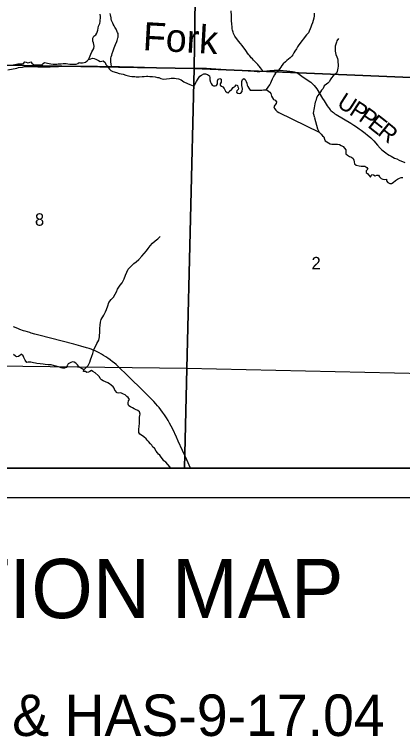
# Model space of a CAD drawing. Extents: x 0 to 34, y 0 to 22.
# Drawn here: x 13.836 to 15.148, y 12.694 to 15.132 of the extents above; entities that cross this region are included whole.
import ezdxf

# ---------------------------------------------------------------- set-up
doc = ezdxf.new("R2010")
doc.units = 0
for name, color, linetype in [('GM_X_Corporation', 7, 'Continuous'), ('GM_X_County_Road', 7, 'Continuous'), ('GM_X_County_Road_Text', 7, 'Continuous'), ('GM_X_Minor_River', 7, 'Continuous'), ('GM_X_Minor_River_Text', 7, 'Continuous'), ('GM_X_Section_Text', 7, 'Continuous'), ('GM_X_State_Route', 7, 'Continuous'), ('GM_X_Township_Road', 7, 'Continuous'), ('SH_Data', 7, 'Continuous'), ('SH_Text', 7, 'Continuous')]:
    doc.layers.add(name, color=color, linetype=linetype)

msp = doc.modelspace()

# ---------------------------------------------------------------- linework, layer by layer
at = {"layer": 'GM_X_Corporation'}
for points in [[(13.4336, 15.974), (14.4583, 15.9623), (14.443, 14.9501), (13.4208, 14.9679)], [(14.4583, 15.9623), (15.4691, 15.9163), (15.4475, 14.9085), (14.443, 14.9501)], [(13.4208, 14.9679), (14.443, 14.9501), (14.4181, 13.9369), (13.4018, 13.9496)], [(14.443, 14.9501), (15.4475, 14.9085), (15.4212, 13.9143), (14.4181, 13.9369)], [(13.3964, 13.6), (14.411, 13.6), (14.4181, 13.9369), (13.4018, 13.9496)], [(14.411, 13.6), (15.4145, 13.6), (15.4212, 13.9143), (14.4181, 13.9369)]]:
    msp.add_lwpolyline(points, close=True, dxfattribs=at)
msp.add_lwpolyline([(10.9052, 15.3502), (10.897, 14.5214), (10.8818, 13.7678), (10.8788, 13.6), (16.4214, 13.6), (16.4212, 13.6609), (16.4339, 14.3806), (16.438, 14.5908), (16.4419, 14.8642), (16.4498, 15.4626)], dxfattribs=at)
at = {"layer": 'GM_X_County_Road'}
msp.add_lwpolyline([(13.8138, 14.9451), (13.8435, 14.9513), (13.8499, 14.9526), (13.8627, 14.9546), (13.867, 14.9552), (13.8765, 14.956), (13.8824, 14.9562), (13.8912, 14.9564), (13.9031, 14.9563), (13.9149, 14.9558), (13.9236, 14.9554), (13.9506, 14.9549), (13.957, 14.9549), (14.0131, 14.9573), (14.0251, 14.9575), (14.0534, 14.9577), (14.117, 14.957), (14.1283, 14.9569), (14.1636, 14.9571), (14.2187, 14.9553), (14.238, 14.9549), (14.3484, 14.9524), (14.3663, 14.952), (14.4643, 14.9512), (14.474, 14.951), (14.4849, 14.9503), (14.5494, 14.9465), (14.5665, 14.9455), (14.6262, 14.9414), (14.6455, 14.9403), (14.6557, 14.9399), (14.6648, 14.9399), (14.6725, 14.9401), (14.6751, 14.9402), (14.6792, 14.9405), (14.6988, 14.9425), (14.7062, 14.9432), (14.7135, 14.9438), (14.7207, 14.9442), (14.7278, 14.944), (14.735, 14.9436), (14.7441, 14.9429), (14.7564, 14.9415), (14.7669, 14.9403), (14.7743, 14.9394), (14.7772, 14.9388), (14.7809, 14.938), (14.785, 14.9368), (14.7881, 14.9357), (14.7977, 14.9306), (14.8121, 14.9207), (14.824, 14.9125), (14.8321, 14.9067), (14.837, 14.9031), (14.8423, 14.8989), (14.8489, 14.892), (14.8532, 14.8868), (14.8573, 14.8813), (14.8768, 14.8488), (14.8822, 14.8401), (14.8926, 14.8241), (14.8958, 14.8195), (14.8981, 14.8164), (14.9033, 14.8105), (14.9056, 14.8082), (14.9108, 14.8034), (14.9136, 14.801), (14.919, 14.797), (14.9228, 14.7945), (14.9724, 14.7651), (14.9827, 14.7588), (14.992, 14.7526), (15.001, 14.7462), (15.008, 14.7411), (15.0214, 14.731), (15.0288, 14.7251), (15.0339, 14.7211), (15.0403, 14.7154), (15.045, 14.7109), (15.0506, 14.7049), (15.0633, 14.6905), (15.0723, 14.6811), (15.0777, 14.6755), (15.0816, 14.672), (15.0861, 14.6683), (15.0906, 14.6648), (15.097, 14.6601), (15.1026, 14.6568), (15.1093, 14.6531), (15.1149, 14.6502), (15.1208, 14.6472), (15.1277, 14.6441), (15.1366, 14.6403), (15.1556, 14.6327)], dxfattribs=at)
at = {"layer": 'GM_X_Minor_River'}
for points in [[(13.8616, 14.9658), (13.8666, 14.967), (13.8711, 14.9723), (13.876, 14.9708), (13.8806, 14.9689), (13.8859, 14.9704), (13.8912, 14.9727), (13.8947, 14.9674), (13.9007, 14.9629), (13.9057, 14.9617), (13.9232, 14.9618), (13.9285, 14.9622), (13.933, 14.9671), (13.9376, 14.9694), (13.9433, 14.969), (13.9478, 14.9679), (13.9531, 14.9668), (13.9588, 14.9656), (13.9668, 14.9645), (13.9786, 14.9645), (13.9839, 14.9653), (13.9884, 14.9657), (13.9938, 14.9657), (14.0002, 14.9665), (14.0067, 14.9661), (14.0112, 14.9661), (14.0158, 14.9654), (14.023, 14.9642), (14.0279, 14.9642), (14.0332, 14.9642), (14.0401, 14.9639), (14.045, 14.9643), (14.0496, 14.9666), (14.0541, 14.9696), (14.0587, 14.9692), (14.0659, 14.9685), (14.0716, 14.9696), (14.0765, 14.9712), (14.0818, 14.9754), (14.0864, 14.9799), (14.0894, 14.9864), (14.0916, 14.9929), (14.0935, 14.9982), (14.0973, 15.0058), (14.1007, 15.0119), (14.1041, 15.0172), (14.1052, 15.0252), (14.1044, 15.0309), (14.1025, 15.0358), (14.101, 15.0423), (14.1006, 15.0476), (14.1009, 15.0521), (14.1043, 15.0586), (14.1104, 15.0628), (14.1146, 15.0689), (14.1172, 15.0788), (14.1187, 15.086), (14.1202, 15.0921), (14.1239, 15.1012), (14.1254, 15.108), (14.1258, 15.1134), (14.1269, 15.1194), (14.1269, 15.1248), (14.1261, 15.1335)], [(14.8488, 15.1361), (14.849, 15.1278), (14.8473, 15.1201), (14.8453, 15.1113), (14.8428, 15.1044), (14.8403, 15.0956), (14.8378, 15.0891), (14.8353, 15.0833), (14.8317, 15.0757), (14.83, 15.0703), (14.8233, 15.0629)], [(14.8233, 15.0629), (14.7973, 15.0299), (14.7924, 15.0227), (14.789, 15.0166), (14.7837, 15.0086), (14.7803, 15.0025), (14.7765, 14.996), (14.7728, 14.9911), (14.7675, 14.9861), (14.7561, 14.977), (14.7515, 14.9724), (14.7436, 14.9656), (14.7394, 14.9595), (14.736, 14.9545), (14.7326, 14.9496), (14.7273, 14.9431), (14.7236, 14.9386), (14.7186, 14.934), (14.7149, 14.9287), (14.7103, 14.9203), (14.7069, 14.9131), (14.7039, 14.9058), (14.7013, 14.9001), (14.6986, 14.8956), (14.6941, 14.8895), (14.6899, 14.883), (14.685, 14.8781)], [(14.9314, 15.0504), (14.9259, 15.0434), (14.9245, 15.0381), (14.922, 15.0319), (14.9199, 15.025), (14.9203, 15.0087), (14.9208, 15.003), (14.9225, 14.997), (14.9257, 14.9891), (14.9278, 14.9834), (14.9287, 14.9777), (14.9292, 14.9709), (14.9294, 14.9637), (14.9299, 14.9576), (14.9293, 14.9511), (14.9262, 14.9393), (14.9241, 14.9339), (14.9181, 14.9296), (14.9125, 14.9249), (14.907, 14.9179), (14.9034, 14.9117), (14.9009, 14.9056), (14.8953, 14.9005), (14.8901, 14.8962), (14.8831, 14.8907), (14.8795, 14.8826), (14.8739, 14.8764), (14.8699, 14.8706), (14.8655, 14.864), (14.8611, 14.8586), (14.8571, 14.8501), (14.8543, 14.8409), (14.8526, 14.8355), (14.8516, 14.8298), (14.8498, 14.8233), (14.8485, 14.8168), (14.8475, 14.8111), (14.8465, 14.8046), (14.8459, 14.7985), (14.8497, 14.7838)], [(14.0866, 14.9804), (14.0943, 14.9822), (14.1, 14.9849), (14.1049, 14.9838), (14.1106, 14.9815), (14.1152, 14.9792), (14.1198, 14.9762), (14.1259, 14.9732), (14.1316, 14.9739), (14.1361, 14.9755), (14.143, 14.9698), (14.1453, 14.9633), (14.1502, 14.9572), (14.154, 14.9523), (14.1567, 14.9478), (14.1616, 14.9428), (14.1681, 14.939), (14.181, 14.9356), (14.1901, 14.933), (14.2038, 14.9304), (14.2126, 14.9273), (14.2209, 14.9251), (14.2259, 14.924), (14.2323, 14.9228), (14.2376, 14.9228), (14.2429, 14.9221), (14.2475, 14.9213), (14.2521, 14.921), (14.257, 14.9214), (14.2672, 14.9225), (14.2741, 14.9229), (14.2821, 14.9233), (14.2866, 14.9237), (14.2934, 14.9229), (14.3026, 14.9222), (14.3113, 14.9211), (14.3193, 14.9196), (14.3238, 14.9188), (14.3303, 14.9158), (14.3356, 14.9143), (14.3409, 14.9139), (14.3497, 14.9143), (14.3603, 14.9158), (14.366, 14.9166), (14.3721, 14.917), (14.3766, 14.917), (14.3827, 14.9155), (14.3907, 14.9148), (14.3998, 14.9114), (14.4085, 14.9042), (14.4203, 14.8992), (14.4283, 14.8958), (14.4401, 14.8909), (14.4458, 14.8955), (14.4511, 14.9054), (14.4545, 14.9118), (14.4575, 14.9168), (14.4624, 14.924), (14.4685, 14.9271), (14.476, 14.9313), (14.4817, 14.9313), (14.4878, 14.9298), (14.4947, 14.9245), (14.4966, 14.9184), (14.4962, 14.9112), (14.4985, 14.9032), (14.5004, 14.8986), (14.5039, 14.8937), (14.5088, 14.8914), (14.5137, 14.891), (14.5183, 14.8926), (14.5217, 14.8975), (14.5221, 14.9032), (14.522, 14.9082), (14.5243, 14.9131), (14.53, 14.9154), (14.5346, 14.9135), (14.535, 14.9089), (14.5342, 14.9032), (14.5316, 14.8983), (14.5308, 14.893), (14.5358, 14.8899), (14.5407, 14.8873), (14.5441, 14.8824), (14.5491, 14.8736), (14.5544, 14.8691), (14.5594, 14.8672), (14.562, 14.8718), (14.5703, 14.8801), (14.5753, 14.8858), (14.5817, 14.89), (14.5855, 14.8946), (14.5901, 14.8923), (14.5908, 14.8874), (14.5927, 14.8828), (14.592, 14.8783), (14.5871, 14.8745), (14.5863, 14.8695), (14.5913, 14.8661), (14.5962, 14.8654), (14.6008, 14.8661)], [(13.832, 14.9616), (13.8377, 14.9631), (13.8423, 14.9643), (13.8468, 14.965), (13.8525, 14.9651), (13.8616, 14.9658)], [(14.6008, 14.8661), (14.6053, 14.8715), (14.6064, 14.8817), (14.6045, 14.8924), (14.6041, 14.9003), (14.6048, 14.906), (14.6063, 14.9121), (14.6109, 14.9159), (14.6154, 14.9125), (14.6185, 14.9061), (14.6212, 14.9), (14.6223, 14.8935), (14.6246, 14.8886), (14.6277, 14.8829), (14.633, 14.8764), (14.6376, 14.8761), (14.6436, 14.8765), (14.6508, 14.8765), (14.6581, 14.8761), (14.6672, 14.8761), (14.6721, 14.8765), (14.6774, 14.8773), (14.685, 14.8781), (14.6896, 14.8766), (14.6945, 14.8735), (14.6995, 14.8701), (14.7029, 14.8652), (14.7037, 14.8606), (14.7048, 14.8557), (14.7079, 14.8511), (14.7117, 14.8451), (14.7166, 14.8428), (14.7212, 14.8371), (14.7205, 14.8318), (14.7159, 14.8253), (14.7121, 14.8207), (14.7148, 14.8147), (14.7198, 14.8093), (14.7243, 14.8044), (14.7293, 14.8014), (14.8657, 14.7347)], [(14.8499, 14.7835), (14.8601, 14.7464), (14.8618, 14.7411), (14.8657, 14.7347), (14.8723, 14.728), (14.8766, 14.7225), (14.882, 14.7192), (14.8834, 14.7112), (14.8862, 14.7052), (14.892, 14.7019), (14.8973, 14.6986), (14.9031, 14.6957), (14.9088, 14.6944), (14.9157, 14.6942), (14.9225, 14.6943), (14.9278, 14.6941), (14.9339, 14.6927), (14.9405, 14.6891), (14.9473, 14.6866), (14.9517, 14.6806), (14.9556, 14.6746), (14.9554, 14.667), (14.9556, 14.6617), (14.9614, 14.6565), (14.9683, 14.6525), (14.9748, 14.65), (14.981, 14.6463), (14.9834, 14.6399), (14.9839, 14.6343), (14.9849, 14.6274), (14.9903, 14.6238), (15.0013, 14.6214), (15.0074, 14.62), (15.0143, 14.6198), (15.02, 14.6199), (15.0265, 14.6159), (15.0301, 14.6099), (15.0249, 14.6045), (15.0243, 14.5988), (15.0297, 14.5943), (15.0336, 14.5891), (15.0395, 14.5824), (15.0434, 14.5912), (15.0488, 14.5906), (15.0545, 14.5873), (15.0602, 14.589), (15.0659, 14.5891), (15.0694, 14.5835), (15.0749, 14.578), (15.081, 14.5762), (15.0871, 14.5748), (15.0927, 14.5765), (15.0936, 14.5708), (15.0976, 14.5645), (15.1045, 14.5616), (15.1102, 14.5617), (15.1154, 14.5645), (15.1236, 14.5716), (15.1299, 14.5759), (15.137, 14.5795), (15.1427, 14.5812), (15.1488, 14.5813)], [(14.0701, 13.9326), (14.085, 13.9463), (14.091, 13.9581), (14.0929, 13.9661), (14.0978, 13.9783), (14.1008, 13.987), (14.1027, 13.9961), (14.1068, 14.0053), (14.1106, 14.0133), (14.1148, 14.0213), (14.1208, 14.0323), (14.1238, 14.0441), (14.1245, 14.0623), (14.1245, 14.0719), (14.1252, 14.0825), (14.1267, 14.0928), (14.129, 14.1019), (14.1377, 14.1167), (14.1437, 14.1278), (14.1471, 14.1358), (14.1513, 14.148), (14.1554, 14.1598), (14.1622, 14.1693), (14.1702, 14.1773), (14.1758, 14.1872), (14.1808, 14.1959), (14.1845, 14.2051), (14.1936, 14.2184), (14.1997, 14.2264), (14.2065, 14.2389), (14.211, 14.2519), (14.2155, 14.2621), (14.2204, 14.2724), (14.2394, 14.2915), (14.2473, 14.2968), (14.256, 14.3052), (14.2663, 14.3162), (14.2738, 14.3246), (14.2818, 14.3338), (14.2882, 14.3418), (14.295, 14.3513), (14.303, 14.3604), (14.3113, 14.3673), (14.3204, 14.3749), (14.3287, 14.3825)], [(14.2227, 13.8108), (14.2204, 13.8161), (14.22, 13.821), (14.2208, 13.8271), (14.2242, 13.8321), (14.22, 13.8389), (14.2154, 13.8427), (14.2101, 13.848), (14.204, 13.8503), (14.1976, 13.8529), (14.193, 13.8541), (14.1885, 13.8533), (14.1831, 13.8541), (14.1755, 13.8639), (14.1725, 13.87), (14.169, 13.8753), (14.1622, 13.8806), (14.1569, 13.8848), (14.1512, 13.8878), (14.1432, 13.8913), (14.136, 13.8947), (14.1299, 13.8985), (14.1261, 13.9034), (14.1234, 13.908), (14.1188, 13.9129), (14.1082, 13.9224), (14.101, 13.9269), (14.096, 13.9296), (14.0911, 13.9269), (14.0858, 13.9242), (14.0808, 13.9235), (14.0755, 13.9265), (14.0698, 13.9265), (14.0702, 13.9326), (14.0649, 13.9356), (14.0573, 13.9402), (14.0527, 13.9443), (14.0493, 13.9489), (14.0436, 13.955), (14.0382, 13.958), (14.0318, 13.9587), (14.0268, 13.9572), (14.0219, 13.9542), (14.017, 13.9526), (14.0136, 13.9454), (14.0106, 13.9401), (14.0045, 13.9374), (13.9988, 13.9378), (13.9935, 13.9393), (13.9885, 13.9408), (13.9768, 13.9442), (13.9718, 13.9461), (13.9604, 13.9487), (13.9555, 13.9487), (13.9502, 13.9491), (13.9395, 13.9502), (13.9331, 13.951), (13.9228, 13.9521), (13.9118, 13.9532), (13.9069, 13.9543), (13.9004, 13.9562), (13.8913, 13.9577), (13.8864, 13.9581), (13.8818, 13.9581), (13.8773, 13.9573), (13.8719, 13.9653), (13.8677, 13.9733), (13.8651, 13.979), (13.859, 13.9854), (13.8537, 13.9809), (13.8491, 13.9771), (13.8442, 13.9763), (13.8389, 13.9778), (13.8324, 13.9839)], [(14.365, 13.6), (14.3645, 13.6004), (14.3607, 13.6049), (14.3546, 13.6121), (14.3474, 13.6201), (14.3413, 13.6254), (14.3367, 13.6315), (14.3318, 13.6376), (14.3272, 13.6437), (14.3226, 13.6471), (14.3192, 13.652), (14.3154, 13.6581), (14.3097, 13.6672), (14.3036, 13.6714), (14.2998, 13.6774), (14.2952, 13.6828), (14.2891, 13.69), (14.2845, 13.6945), (14.2807, 13.6991), (14.2735, 13.7059), (14.2651, 13.7112), (14.2602, 13.7154), (14.2568, 13.7211), (14.256, 13.7257), (14.2563, 13.7336), (14.2571, 13.7386), (14.2578, 13.7439), (14.2586, 13.7489), (14.2586, 13.758), (14.2589, 13.7652), (14.2585, 13.7728), (14.26, 13.7778), (14.2611, 13.7827), (14.2589, 13.7899), (14.2524, 13.7945), (14.2455, 13.7986), (14.2406, 13.8005), (14.2353, 13.804), (14.2277, 13.807), (14.2227, 13.8108)]]:
    msp.add_lwpolyline(points, dxfattribs=at)
at = {"layer": 'GM_X_State_Route'}
msp.add_lwpolyline([(14.4306, 13.6), (14.418, 13.6281), (14.3893, 13.6914), (14.3833, 13.7044), (14.3707, 13.732), (14.3657, 13.7419), (14.3602, 13.7524), (14.3555, 13.7608), (14.3496, 13.7706), (14.3435, 13.7799), (14.3367, 13.7896), (14.3245, 13.8055), (14.3195, 13.8111), (14.3138, 13.8175), (14.3067, 13.8254), (14.299, 13.8334), (14.2831, 13.8493), (14.2084, 13.922), (14.1966, 13.9332), (14.1794, 13.9497), (14.1725, 13.9556), (14.1677, 13.9594), (14.1593, 13.9661), (14.1518, 13.9718), (14.1445, 13.9766), (14.1373, 13.981), (14.1301, 13.9851), (14.1217, 13.9898), (14.1158, 13.9928), (14.1091, 13.9958), (14.1019, 13.9989), (14.0951, 14.0016), (14.088, 14.0041), (14.0789, 14.007), (14.0607, 14.0123), (14.0365, 14.0187), (13.9182, 14.0493), (13.9048, 14.0529), (13.8922, 14.0563), (13.8874, 14.0577), (13.8726, 14.0622), (13.8668, 14.0641), (13.8546, 14.0686), (13.8476, 14.0714), (13.8327, 14.0779)], dxfattribs=at)
at = {"layer": 'GM_X_Township_Road'}
for points in [[(14.6751, 14.9402), (14.6727, 14.9443), (14.6718, 14.9458), (14.6667, 14.9529), (14.6642, 14.9559), (14.6616, 14.9589), (14.6582, 14.9627), (14.6539, 14.9673), (14.6494, 14.9722), (14.6442, 14.9778), (14.6399, 14.9824), (14.6364, 14.9862), (14.6314, 14.9921), (14.628, 14.9961), (14.624, 15.0014), (14.6199, 15.0069), (14.6152, 15.0139), (14.6112, 15.0199), (14.6056, 15.0273), (14.6002, 15.0336), (14.5936, 15.0417), (14.5874, 15.0498), (14.5835, 15.0551), (14.5809, 15.0592), (14.5785, 15.0633), (14.5763, 15.0678), (14.5747, 15.0719), (14.5734, 15.0758), (14.5725, 15.0796), (14.5718, 15.0838), (14.5712, 15.0887), (14.5703, 15.1004), (14.5698, 15.1101), (14.5692, 15.1277), (14.5683, 15.1443)], [(14.1636, 14.9571), (14.1625, 14.9638), (14.1614, 14.9723), (14.1613, 14.9744), (14.1615, 14.9796), (14.162, 14.984), (14.1629, 14.9892), (14.1646, 14.9948), (14.1663, 15.0008), (14.1692, 15.0092), (14.1733, 15.02), (14.1779, 15.0308), (14.1817, 15.0405), (14.1832, 15.0447), (14.1846, 15.0491), (14.1858, 15.0532), (14.1864, 15.056), (14.1868, 15.0603), (14.1867, 15.0636), (14.1859, 15.0675), (14.1847, 15.0711), (14.1835, 15.074), (14.182, 15.0769), (14.1793, 15.082), (14.175, 15.0894), (14.1725, 15.094), (14.1697, 15.0996), (14.1682, 15.1027), (14.1651, 15.1099), (14.1643, 15.1122), (14.1628, 15.1176), (14.1622, 15.1202), (14.1605, 15.1305), (14.1599, 15.1349)]]:
    msp.add_lwpolyline(points, dxfattribs=at)
at = {"layer": 'SH_Data'}
for points in [[(10.5, 20.5), (17.5, 20.5), (17.5, 13.5), (10.5, 13.5)], [(10.6, 20.4), (17.4, 20.4), (17.4, 13.6), (10.6, 13.6)]]:
    msp.add_lwpolyline(points, close=True, dxfattribs=at)

# ---------------------------------------------------------------- texts
at = {"layer": 'GM_X_County_Road_Text'}
for s, rotation, p in [('U', 327.2617, (14.9223, 14.8234)), ('P', 326.7883, (14.9643, 14.7964)), ('P', 324.5319, (14.9959, 14.7757)), ('E', 321.9687, (15.0265, 14.7539)), ('R', 321.1275, (15.0598, 14.7278))]:
    msp.add_text(s, height=0.0568, rotation=rotation, dxfattribs=at).set_placement(p)
at = {"layer": 'GM_X_Minor_River_Text'}
msp.add_text('Fork', height=0.0947, rotation=356.8219, dxfattribs=at).set_placement((14.2682, 15.0121))
at = {"layer": 'GM_X_Section_Text'}
for s, p in [('8', (13.9052, 14.4188)), ('2', (14.8398, 14.2716))]:
    msp.add_text(s, height=0.0419, rotation=0, dxfattribs=at).set_placement(p)
at = {"layer": 'SH_Text'}
for s, height, p in [('LOCATION MAP', 0.2, (12.9269, 13.0938)), ('HAS-9-15.52 & HAS-9-17.04', 0.14, (12.6938, 12.6959))]:
    msp.add_text(s, height=height, dxfattribs=at).set_placement(p)

doc.saveas('drawing.dxf')
